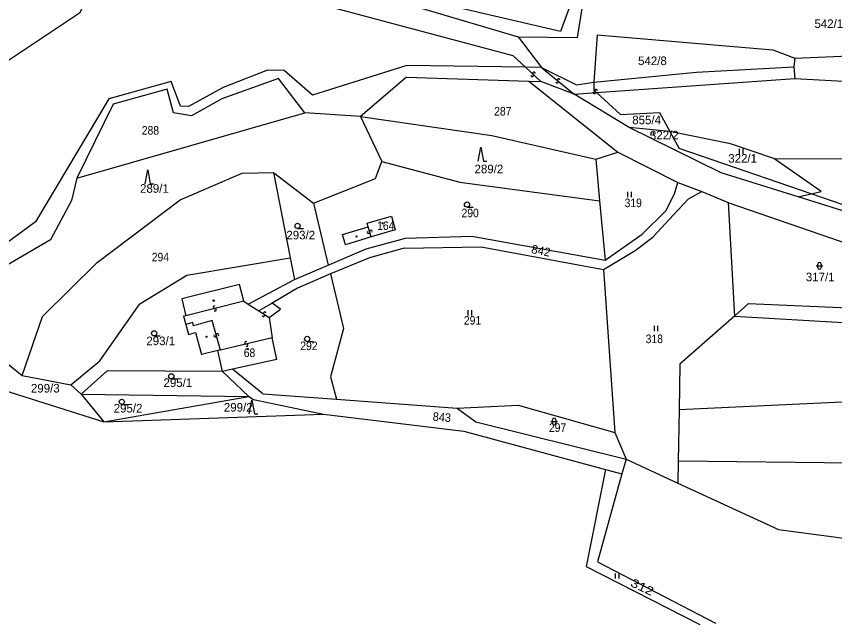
# Model space of a CAD drawing. Extents: x -680102 to -677253, y -1007548 to -1006096.
# Drawn here: x -679757 to -679518.8, y -1007499.2 to -1007322.1 of the extents above; entities that cross this region are included whole.
import ezdxf
from ezdxf.enums import TextEntityAlignment as Align

# ---------------------------------------------------------------- set-up
doc = ezdxf.new("R2010")
doc.units = 0
for name, color, linetype, lineweight in [('1', 7, 'Continuous', 25), ('25', 7, 'Continuous', 25), ('4', 7, 'Continuous', 25)]:
    doc.layers.add(name, color=color, linetype=linetype, lineweight=lineweight)
doc.layers.add('18', color=7, linetype='Continuous')
doc.layers.add('19', color=7, linetype='Continuous')

msp = doc.modelspace()

# ---------------------------------------------------------------- linework, layer by layer
at = {"layer": '1'}
for p, q in [((-679610.92, -1007328.07), (-679604.16, -1007337.04)), ((-679587.95, -1007327.5), (-679588.97, -1007341.34)), ((-679587.95, -1007327.5), (-679536.79, -1007331.88)), ((-679536.79, -1007331.88), (-679530.47, -1007334.35)), ((-679612.54, -1007333.58), (-679608.85, -1007336.97)), ((-679559.06, -1007338.39), (-679530.69, -1007336.87)), ((-679680.73, -1007340.22), (-679697.2, -1007346.12)), ((-679643.48, -1007339.82), (-679656.81, -1007351.32)), ((-679643.48, -1007339.82), (-679607.87, -1007341)), ((-679588.97, -1007341.34), (-679559.06, -1007338.39)), ((-679607.87, -1007341), (-679604.38, -1007341.08)), ((-679607.87, -1007341), (-679581.98, -1007361.69)), ((-679713.17, -1007343.37), (-679728.84, -1007347.68)), ((-679711.24, -1007350.19), (-679713.17, -1007343.37)), ((-679588.19, -1007344.33), (-679581.21, -1007350.75)), ((-679697.2, -1007346.12), (-679706.05, -1007351.13)), ((-679728.84, -1007347.68), (-679739.39, -1007369.2)), ((-679706.05, -1007351.13), (-679711.24, -1007350.19)), ((-679656.81, -1007351.32), (-679673.1, -1007350.19)), ((-679656.81, -1007351.32), (-679618.65, -1007356.83)), ((-679656.81, -1007351.32), (-679650.63, -1007364.42)), ((-679581.21, -1007350.75), (-679569.8, -1007350.13)), ((-679536.5, -1007363.53), (-679549.18, -1007359.23)), ((-679588.4, -1007363.66), (-679587.33, -1007375.83)), ((-679652.53, -1007369.36), (-679650.63, -1007364.42)), ((-679650.63, -1007364.42), (-679627.95, -1007370.4)), ((-679682.14, -1007367.6), (-679670.54, -1007376.56)), ((-679670.54, -1007376.56), (-679652.53, -1007369.36)), ((-679670.54, -1007376.56), (-679666.24, -1007394.56)), ((-679549.86, -1007376.28), (-679548, -1007409.36)), ((-679644.14, -1007389.64), (-679654.19, -1007392.44)), ((-679644.14, -1007389.64), (-679621.72, -1007389.22)), ((-679621.72, -1007389.22), (-679586.14, -1007395.78)), ((-679707.45, -1007397.52), (-679677.35, -1007392.45)), ((-679677.35, -1007392.45), (-679676.02, -1007398.74)), ((-679654.19, -1007392.44), (-679665.63, -1007397.05)), ((-679721.09, -1007405.77), (-679707.45, -1007397.52)), ((-679665.63, -1007397.05), (-679675.19, -1007401.25)), ((-679665.63, -1007397.05), (-679661.84, -1007413.03)), ((-679586.14, -1007395.78), (-679582.79, -1007443.24)), ((-679690.83, -1007405.06), (-679692.05, -1007400.19)), ((-679732.68, -1007422.41), (-679721.09, -1007405.77)), ((-679689.51, -1007405.91), (-679686.45, -1007407.87)), ((-679680.14, -1007407.4), (-679682.55, -1007405.58)), ((-679707.68, -1007409.27), (-679708.4, -1007409.45)), ((-679683.46, -1007409.79), (-679680.14, -1007407.4)), ((-679708.4, -1007409.45), (-679707.71, -1007411.86)), ((-679683.46, -1007409.79), (-679682.55, -1007415.75)), ((-679707.71, -1007411.86), (-679706.89, -1007414.74)), ((-679681.2, -1007422.01), (-679682.55, -1007415.75)), ((-679766.75, -1007417.51), (-679755.37, -1007426.71)), ((-679698.35, -1007419.44), (-679703.15, -1007420.56)), ((-679697.02, -1007425.49), (-679698.35, -1007419.44)), ((-679681.2, -1007422.01), (-679694.07, -1007424.84)), ((-679730.56, -1007425.3), (-679738.17, -1007432.14)), ((-679697.02, -1007425.49), (-679730.56, -1007425.3)), ((-679694.07, -1007424.84), (-679697.02, -1007425.49)), ((-679697.02, -1007425.49), (-679689.32, -1007432.76)), ((-679685.31, -1007432.01), (-679694.07, -1007424.84)), ((-679768.72, -1007428.41), (-679731.53, -1007440.19)), ((-679741.21, -1007429.41), (-679738.17, -1007432.14)), ((-679738.17, -1007432.14), (-679689.32, -1007432.76)), ((-679689.32, -1007432.76), (-679688.04, -1007433.65)), ((-679688.04, -1007433.65), (-679667.67, -1007437.93)), ((-679731.53, -1007440.19), (-679667.67, -1007437.93)), ((-679667.67, -1007437.93), (-679626.73, -1007442.87)), ((-679626.73, -1007442.87), (-679585.56, -1007454.07)), ((-679582.79, -1007443.24), (-679579.54, -1007451.05)), ((-679495.67, -1007452.42), (-679564.37, -1007451.65)), ((-679585.56, -1007454.07), (-679591.13, -1007482.25)), ((-679585.56, -1007454.07), (-679580.74, -1007455.34)), ((-679535.19, -1007471.47), (-679509.2, -1007475)), ((-679591.13, -1007482.25), (-679558.04, -1007499.19)), ((-679587.89, -1007480.92), (-679553.55, -1007498.72))]:
    msp.add_line(p, q, dxfattribs=at)
for points in [[(-679722.75, -1007280.79), (-679718.93, -1007292.15), (-679713.9, -1007300.35), (-679705.61, -1007308.64), (-679612.54, -1007333.58)], [(-679690.78, -1007287.62), (-679697.83, -1007302.32), (-679610.92, -1007328.07), (-679593.69, -1007328.25), (-679589.32, -1007301.17), (-679598.63, -1007326.55), (-679652.45, -1007313.98)], [(-679724.02, -1007294.07), (-679738.68, -1007321.18), (-679759.61, -1007335.18), (-679777.7, -1007359.21)], [(-679530.41, -1007340.21), (-679500.33, -1007341.85), (-679488.03, -1007336.83), (-679465.4, -1007337.14), (-679447.34, -1007331.48), (-679433.57, -1007319.93), (-679420.33, -1007319.87), (-679417.19, -1007318.87), (-679415.6, -1007316.76), (-679418.86, -1007315.49)], [(-679530.47, -1007334.35), (-679460.89, -1007331.33), (-679450.72, -1007329.05), (-679442.85, -1007323.05)], [(-679530.47, -1007334.35), (-679530.69, -1007336.87), (-679530.41, -1007340.21)], [(-679679.12, -1007337.93), (-679683.93, -1007337.81), (-679696.85, -1007342.84), (-679706.91, -1007348.37), (-679709.28, -1007348.27), (-679711.94, -1007341.07), (-679730.09, -1007346.1)], [(-679643.32, -1007336.44), (-679670.84, -1007345.12), (-679679.12, -1007337.93)], [(-679604.16, -1007337.04), (-679608.85, -1007336.97), (-679643.32, -1007336.44)], [(-679604.16, -1007337.04), (-679593.95, -1007342.06), (-679588.97, -1007341.34)], [(-679739.39, -1007369.2), (-679673.1, -1007350.19), (-679680.73, -1007340.22)], [(-679594.66, -1007344.79), (-679588.19, -1007344.33), (-679530.41, -1007340.21)], [(-679488.66, -1007386.35), (-679498.55, -1007384.38), (-679529.47, -1007374.69), (-679551.85, -1007367.67), (-679565.44, -1007361.02), (-679578.65, -1007354.47), (-679594.66, -1007344.79), (-679604.38, -1007341.08)], [(-679730.09, -1007346.1), (-679751.49, -1007381.96), (-679770.73, -1007396.14)], [(-679569.8, -1007350.13), (-679566.8, -1007355.67), (-679564.14, -1007360.58)], [(-679549.18, -1007359.23), (-679566.8, -1007355.67), (-679578.65, -1007354.47)], [(-679618.65, -1007356.83), (-679588.4, -1007363.66), (-679581.98, -1007361.69)], [(-679581.98, -1007361.69), (-679564.46, -1007370.54), (-679557.5, -1007373.16)], [(-679495.26, -1007384.27), (-679525.72, -1007373.79), (-679564.14, -1007360.58)], [(-679522.79, -1007373.09), (-679536.5, -1007363.53), (-679497.8, -1007363.63), (-679497.7, -1007367.9), (-679448.44, -1007362.22), (-679429.92, -1007361.19)], [(-679755.37, -1007426.71), (-679749.4, -1007409.47), (-679733.54, -1007393.77), (-679709.32, -1007375.51), (-679691.25, -1007367.83)], [(-679691.25, -1007367.83), (-679682.14, -1007367.6), (-679677.35, -1007392.45)], [(-679739.39, -1007369.2), (-679741.02, -1007375.78), (-679747.12, -1007387.18), (-679766.95, -1007398.78)], [(-679627.95, -1007370.4), (-679587.33, -1007375.83), (-679585.62, -1007393.07)], [(-679574.9, -1007385.54), (-679567.99, -1007378.71), (-679565.43, -1007373.84), (-679564.46, -1007370.54)], [(-679586.14, -1007395.78), (-679576.94, -1007390.32), (-679571.74, -1007386.39), (-679565.77, -1007379.9), (-679561.42, -1007375.21), (-679557.5, -1007373.16)], [(-679557.5, -1007373.16), (-679549.86, -1007376.28), (-679549.6, -1007376.39), (-679409.65, -1007424.66), (-679396.29, -1007429.27), (-679283.7, -1007440.7), (-679277.3, -1007443.79), (-679273.41, -1007446.8)], [(-679529.47, -1007374.69), (-679525.72, -1007373.79), (-679522.79, -1007373.09)], [(-679624.46, -1007386.16), (-679585.62, -1007393.07), (-679574.9, -1007385.54)], [(-679655.16, -1007389.83), (-679643.73, -1007386.67), (-679624.46, -1007386.16)], [(-679676.02, -1007398.74), (-679666.24, -1007394.56), (-679655.16, -1007389.83)], [(-679690.83, -1007405.06), (-679689.51, -1007405.91), (-679676.02, -1007398.74)], [(-679692.05, -1007400.19), (-679708.9, -1007404.4), (-679707.68, -1007409.27)], [(-679675.19, -1007401.25), (-679682.55, -1007405.58), (-679686.45, -1007407.87)], [(-679543.91, -1007405.75), (-679548, -1007409.36), (-679563.86, -1007423.37)], [(-679543.91, -1007405.75), (-679497.1, -1007407.72), (-679449.59, -1007417.57)], [(-679548, -1007409.36), (-679497.99, -1007412.27), (-679441.58, -1007422.87)], [(-679706.89, -1007414.74), (-679704.87, -1007414.16), (-679703.15, -1007420.56)], [(-679661.84, -1007413.03), (-679665.63, -1007427.1), (-679663.83, -1007433.59)], [(-679755.37, -1007426.71), (-679741.21, -1007429.41), (-679732.68, -1007422.41)], [(-679563.86, -1007423.37), (-679564.1, -1007436.71), (-679564.37, -1007451.65), (-679564.48, -1007457.98)], [(-679738.17, -1007432.14), (-679731.53, -1007440.19), (-679689.32, -1007432.76)], [(-679685.31, -1007432.01), (-679663.83, -1007433.59), (-679628.71, -1007436.21)], [(-679628.71, -1007436.21), (-679610.97, -1007435.28), (-679582.79, -1007443.24)], [(-679299.68, -1007457.86), (-679406.38, -1007449.32), (-679479.4, -1007434.83), (-679512.45, -1007434.27), (-679564.1, -1007436.71)], [(-679628.71, -1007436.21), (-679623.28, -1007440.13), (-679579.54, -1007451.05)], [(-679579.54, -1007451.05), (-679580.74, -1007455.34), (-679587.89, -1007480.92)], [(-679579.54, -1007451.05), (-679564.48, -1007457.98), (-679535.19, -1007471.47)]]:
    msp.add_lwpolyline(points, dxfattribs=at)
msp.add_lwpolyline([(-679662.1, -1007385.68), (-679654.63, -1007383.38), (-679654.94, -1007382.32), (-679647.8, -1007380.3), (-679646.72, -1007384.28), (-679653.77, -1007386.33), (-679661.2, -1007388.67)], close=True, dxfattribs=at)
at = {"layer": '25'}
for p, q in [((-679572.296, -1007356.852), (-679572.296, -1007355.847)), ((-679571.603, -1007356.852), (-679571.603, -1007355.847)), ((-679546.547, -1007362.245), (-679546.547, -1007360.745)), ((-679545.513, -1007362.245), (-679545.513, -1007360.745)), ((-679578.997, -1007374.735), (-679578.997, -1007373.235)), ((-679577.963, -1007374.735), (-679577.963, -1007373.235)), ((-679625.85, -1007377.66), (-679624.1, -1007377.66)), ((-679675.16, -1007383.87), (-679673.41, -1007383.87)), ((-679524.24, -1007394.75), (-679522.24, -1007394.75)), ((-679523.74, -1007395.25), (-679523.74, -1007394.25)), ((-679522.74, -1007394.25), (-679522.74, -1007395.25)), ((-679625.507, -1007409.185), (-679625.507, -1007407.685)), ((-679624.473, -1007409.185), (-679624.473, -1007407.685)), ((-679571.307, -1007413.765), (-679571.307, -1007412.265)), ((-679570.273, -1007413.765), (-679570.273, -1007412.265)), ((-679716.92, -1007415.15), (-679715.17, -1007415.15)), ((-679672.37, -1007416.77), (-679670.62, -1007416.77)), ((-679711.92, -1007427.66), (-679710.17, -1007427.66)), ((-679726.34, -1007435.09), (-679724.59, -1007435.09)), ((-679601.5, -1007440.07), (-679599.5, -1007440.07)), ((-679601, -1007440.57), (-679601, -1007439.57)), ((-679600, -1007439.57), (-679600, -1007440.57)), ((-679582.617, -1007485.785), (-679582.617, -1007484.285)), ((-679581.583, -1007485.785), (-679581.583, -1007484.285))]:
    msp.add_line(p, q, dxfattribs=at)
for points in [[(-679622.56, -1007364.25), (-679621.81, -1007360.25), (-679621.06, -1007364.25), (-679620.06, -1007364.25)], [(-679719.55, -1007370.85), (-679718.8, -1007366.85), (-679718.05, -1007370.85), (-679717.05, -1007370.85)], [(-679689.22, -1007437.83), (-679688.47, -1007433.83), (-679687.72, -1007437.83), (-679686.72, -1007437.83)]]:
    msp.add_lwpolyline(points, dxfattribs=at)
for centre, radius in [((-679625.85, -1007376.91), 0.75), ((-679675.16, -1007383.12), 0.75), ((-679650.47, -1007382.33), 0.175), ((-679658.01, -1007386.22), 0.175), ((-679699.61, -1007404.87), 0.175), ((-679716.92, -1007414.4), 0.75), ((-679701.67, -1007415.38), 0.175), ((-679672.37, -1007416.02), 0.75), ((-679689.71, -1007418.97), 0.175), ((-679711.92, -1007426.91), 0.75), ((-679726.34, -1007434.34), 0.75)]:
    msp.add_circle(centre, radius, dxfattribs=at)
for centre, radius, start, end in [((-679606.863, -1007339.299), 0.369, 174.70844, 46.5969), ((-679606.359, -1007338.761), 0.368, 354.51656, 226.98433), ((-679599.175, -1007340.637), 0.368, 357.89749, 230.29597), ((-679599.647, -1007341.202), 0.368, 177.97822, 50.07252), ((-679588.792, -1007344.279), 0.368, 174.86327, 46.71091), ((-679588.29, -1007343.74), 0.368, 354.59261, 227.20441), ((-679654.553, -1007384.96), 0.367, 143.61111, 15.81682), ((-679653.845, -1007384.761), 0.369, 323.72366, 195.86158), ((-679523.24, -1007394.25), 0.5, 0.101, 180.00143), ((-679523.24, -1007395.25), 0.5, 180.10243, 0.00286), ((-679699.345, -1007406.811), 0.368, 51.51083, 283.32279), ((-679699.174, -1007407.527), 0.367, 231.19183, 103.54511), ((-679685.153, -1007409.138), 0.368, 184.51954, 56.51671), ((-679684.749, -1007408.522), 0.368, 4.48252, 236.87352), ((-679699.174, -1007415.079), 0.368, 143.65811, 15.62436), ((-679698.465, -1007414.883), 0.368, 323.38124, 195.3388), ((-679690.15, -1007417.15), 0.368, 50.5138, 282.25894), ((-679689.989, -1007417.869), 0.368, 230.10131, 102.71537), ((-679600.5, -1007439.57), 0.5, 0.101, 180.00143), ((-679600.5, -1007440.57), 0.5, 180.10243, 0.00286)]:
    msp.add_arc(centre, radius, start, end, dxfattribs=at)
at = {"layer": '4'}
for p, q in [((-679608.85, -1007336.97), (-679604.38, -1007341.08)), ((-679604.16, -1007337.04), (-679594.66, -1007344.79)), ((-679588.97, -1007341.34), (-679588.89, -1007343.69)), ((-679588.89, -1007343.69), (-679588.19, -1007344.33)), ((-679653.77, -1007386.33), (-679654.63, -1007383.38)), ((-679690.83, -1007405.06), (-679707.68, -1007409.27)), ((-679686.45, -1007407.87), (-679683.46, -1007409.79)), ((-679682.55, -1007415.75), (-679697.6, -1007419.26)), ((-679697.6, -1007419.26), (-679698.35, -1007419.44))]:
    msp.add_line(p, q, dxfattribs=at)
msp.add_lwpolyline([(-679697.6, -1007419.26), (-679700.04, -1007410.7), (-679705.42, -1007412.24), (-679705.7, -1007411.28), (-679707.71, -1007411.86)], dxfattribs=at)

# ---------------------------------------------------------------- texts
at = {"layer": '18'}
for s, p in [('542/1', (-679520.54, -1007325.53)), ('542/8', (-679571.88, -1007336.33)), ('855/4', (-679573.569, -1007353.54)), ('322/2', (-679568.419, -1007357.96)), ('322/1', (-679545.63, -1007364.72)), ('293/2', (-679674.25, -1007387.05)), ('317/1', (-679523.04, -1007399.25))]:
    msp.add_text(s, height=2.5, dxfattribs=at).set_placement(p, align=Align.CENTER)
at = {"layer": '18', "width": 0.9}
for s, p in [('287', (-679617.94, -1007351.01)), ('288', (-679720.51, -1007356.57)), ('319', (-679579.98, -1007377.67)), ('290', (-679627.44, -1007380.62)), ('294', (-679717.61, -1007393.45)), ('291', (-679626.76, -1007411.87)), ('292', (-679674.38, -1007419.3)), ('297', (-679602, -1007443.09))]:
    msp.add_text(s, height=2.5, dxfattribs=at).set_placement(p)
at = {"layer": '18'}
for s, p in [('289/2', (-679623.66, -1007367.81)), ('289/1', (-679721.02, -1007373.49)), ('293/1', (-679719.19, -1007417.85)), ('295/1', (-679714.19, -1007430.02)), ('299/3', (-679752.78, -1007431.63)), ('295/2', (-679728.7, -1007437.45)), ('299/2', (-679696.62, -1007437.19))]:
    msp.add_text(s, height=2.5, dxfattribs=at).set_placement(p)
msp.add_text('842', height=2.5, rotation=348.603, dxfattribs=at).set_placement((-679607.305, -1007391.014))
at = {"layer": '18', "width": 0.9}
msp.add_text('318', height=2.5, dxfattribs=at).set_placement((-679571.329, -1007417.25), align=Align.CENTER)
at = {"layer": '18'}
for s, rotation, width, p in [('843', 355.303, 0.95, (-679635.905, -1007439.818)), ('312', 334.603, 1.25, (-679578.504, -1007487.886))]:
    msp.add_text(s, height=2.5, rotation=rotation, dxfattribs=dict(at, width=width)).set_placement(p)
at = {"layer": '19', "width": 0.9}
for s, p in [('164', (-679652.01, -1007384.33)), ('68', (-679690.84, -1007421.3))]:
    msp.add_text(s, height=2.5, dxfattribs=at).set_placement(p)

doc.saveas('drawing.dxf')
